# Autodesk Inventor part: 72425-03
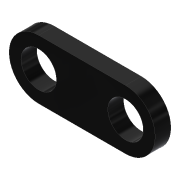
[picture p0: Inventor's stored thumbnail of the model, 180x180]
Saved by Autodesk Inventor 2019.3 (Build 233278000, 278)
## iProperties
Created: 2012-10
Part Number: 72425-03
Material: Ogólny
Document SubType Name: Modeling
Designer: CADENGINEERING4
Density: 1 g/cm^3
Appearance: Gładki — czarny
Author: CADENGINEERING4
Revision Number: ÈÎºÎ
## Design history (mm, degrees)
feature "ÊäÈë1"
node "Bryła1"
